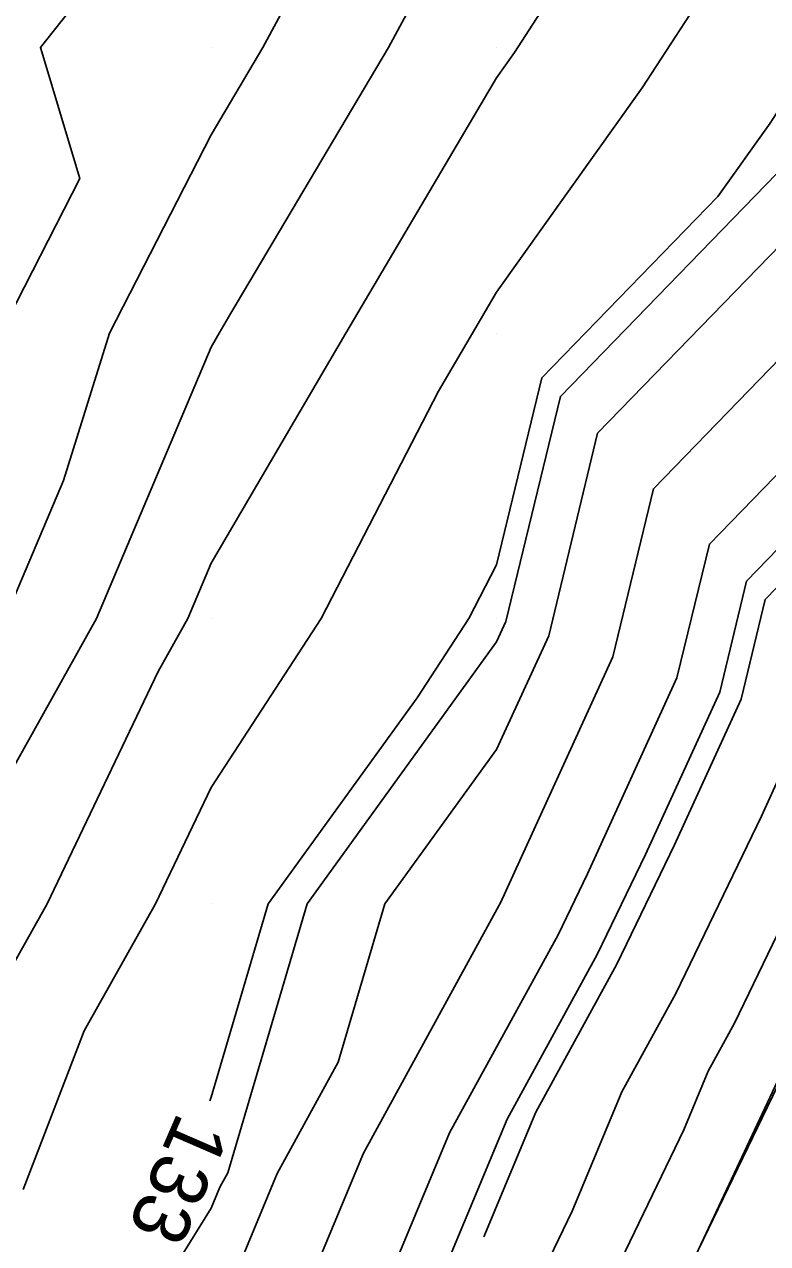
# Model space of a CAD drawing. Extents: x 2354170 to 2357230, y 866100 to 868290.
# Drawn here: x 2355193.44 to 2355219.46, y 866318.1 to 866360.82 of the extents above; entities that cross this region are included whole.
import ezdxf

# ---------------------------------------------------------------- set-up
doc = ezdxf.new("R2010")
doc.units = 0
for name, color, linetype in [('Default', 7, 'Continuous'), ('DTM Contours Major', 7, 'Continuous'), ('DTM Contours Minor', 7, 'Continuous'), ('Exist DTM QL2 LIDAR Elevation Point', 7, 'Continuous'), ('PH Exist DTM Breakline', 7, 'Continuous')]:
    doc.layers.add(name, color=color, linetype=linetype)

msp = doc.modelspace()

# ---------------------------------------------------------------- linework, layer by layer
at = {"layer": 'Default'}
for points in [[(2355191.499, 866299.8), (2355194.3, 866304.328), (2355196.889, 866310.002), (2355199.974, 866314.981), (2355202.29, 866320.553), (2355204.427, 866324.456), (2355206.063, 866330.003), (2355209.974, 866335.409), (2355211.797, 866339.401), (2355213.512, 866346.491), (2355221.537, 866354.768), (2355222.975, 866357.505), (2355230.701, 866372.146), (2355231.769, 866374.181), (2355238.322, 866388.575), (2355240.533, 866394.009), (2355250.162, 866415.374), (2355252.053, 866420.135), (2355254.413, 866426.352), (2355262.121, 866446.655), (2355264.794, 866454.48), (2355265.461, 866456.693), (2355266.805, 866460.625), (2355273.433, 866482.8)], [(2355190.844, 866286.344), (2355193.672, 866291.617), (2355196.759, 866299.104), (2355201.731, 866307.143), (2355204.812, 866313.534), (2355208.326, 866321.988), (2355212.125, 866328.925), (2355213.154, 866331.059), (2355216.287, 866337.919), (2355217.422, 866342.611), (2355222.733, 866348.088), (2355228.658, 866359.37), (2355233.375, 866368.308), (2355237.776, 866376.692), (2355241.498, 866384.869), (2355248.469, 866402.004), (2355252.795, 866411.603), (2355257.385, 866423.159), (2355258.204, 866425.317), (2355260.879, 866432.362), (2355268.147, 866453.642), (2355268.327, 866454.238), (2355272.099, 866465.271)], [(2355190.29, 866290.14), (2355194.129, 866299.452), (2355200.313, 866309.451), (2355200.907, 866310.684), (2355205.308, 866321.271), (2355210.065, 866329.957), (2355210.108, 866330.047), (2355214.042, 866338.66), (2355215.467, 866344.551), (2355222.135, 866351.428), (2355225.816, 866358.437), (2355232.038, 866370.227), (2355234.772, 866375.436), (2355239.91, 866386.722), (2355244.501, 866398.007), (2355251.479, 866413.489), (2355254.719, 866421.647), (2355256.309, 866425.835), (2355261.5, 866439.509), (2355266.47, 866454.061), (2355266.894, 866455.466), (2355269.452, 866462.948)], [(2355186.69, 866323.421), (2355189.974, 866329.157), (2355190.45, 866330.003), (2355190.883, 866330.912), (2355195.961, 866340.003), (2355199.974, 866349.514), (2355200.26, 866350.003), (2355200.672, 866350.702), (2355206.189, 866360.003), (2355209.974, 866367.025), (2355211.068, 866368.721), (2355211.919, 866370.333), (2355212.511, 866372.54), (2355215.529, 866380.003), (2355216.515, 866383.462), (2355219.974, 866388.355), (2355221.061, 866390.022), (2355221.375, 866391.404), (2355225.429, 866400.004), (2355226.321, 866403.657), (2355228.699, 866410.004), (2355229.946, 866413.048)], [(2355199.927, 866323.11), (2355199.974, 866323.23), (2355201.971, 866330.003), (2355207.193, 866337.223), (2355209.001, 866340.003), (2355209.974, 866341.886), (2355211.557, 866348.431), (2355217.719, 866354.786), (2355219.548, 866357.353), (2355220.076, 866358.171), (2355227.928, 866373.051), (2355228.294, 866374.417), (2355236.246, 866389.93), (2355236.481, 866390.29), (2355236.571, 866390.686), (2355238.576, 866394.476), (2355245.955, 866410.847)], [(2355209.531, 866318.342), (2355211.345, 866322.706), (2355214.185, 866327.893), (2355216.2, 866332.071), (2355218.532, 866337.178), (2355219.377, 866340.671), (2355223.331, 866344.748), (2355231.499, 866360.302), (2355234.712, 866366.39), (2355240.779, 866377.948), (2355243.086, 866383.016), (2355252.437, 866406.002), (2355253.237, 866407.776)], [(2355192.613, 866350.003), (2355195.385, 866355.415), (2355194.002, 866360.003), (2355199.974, 866367.561)], [(2355189.974, 866322.426), (2355194.241, 866330.003), (2355198.123, 866338.152), (2355199.157, 866340.003), (2355199.974, 866341.939), (2355204.695, 866350.003), (2355209.974, 866358.947), (2355210.602, 866359.829), (2355214.071, 866365.205)], [(2355192.766, 866340.003), (2355194.803, 866344.833), (2355196.416, 866350.003), (2355199.974, 866356.948), (2355201.785, 866360.003), (2355203.903, 866363.933)], [(2355193.232, 866276.307), (2355203.819, 866296.046), (2355204.649, 866298.059), (2355205.986, 866300.22), (2355216.526, 866322.084), (2355217.381, 866324.141), (2355218.305, 866325.829), (2355222.291, 866334.095), (2355223.022, 866335.695), (2355223.287, 866336.79), (2355224.526, 866338.068), (2355237.182, 866362.166)], [(2355193.392, 866320.003), (2355195.53, 866325.559), (2355198.033, 866330.003), (2355199.974, 866334.078), (2355203.826, 866340.003), (2355207.94, 866347.969), (2355209.131, 866350.003), (2355209.974, 866351.431), (2355215.075, 866358.591), (2355217.073, 866361.688)], [(2355192.436, 866279.652), (2355200.437, 866294.57), (2355202.019, 866298.407), (2355204.567, 866302.527), (2355212.621, 866319.234), (2355214.363, 866323.424), (2355216.245, 866326.861), (2355219.246, 866333.083), (2355220.777, 866336.436), (2355221.332, 866338.73), (2355223.928, 866341.408), (2355234.34, 866361.234)], [(2355215.75, 866315.225), (2355217.04, 866317.9), (2355220.322, 866324.685), (2355220.344, 866324.727), (2355220.368, 866324.772), (2355220.395, 866324.821), (2355225.21, 866334.753), (2355225.276, 866334.873), (2355225.345, 866335.007), (2355225.416, 866335.152), (2355225.486, 866335.304), (2355238.182, 866358.692), (2355238.772, 866359.68), (2355239.335, 866360.958)]]:
    msp.add_lwpolyline(points, dxfattribs=at)
at = {"layer": 'DTM Contours Major'}
msp.add_lwpolyline([(2355215.75, 866315.225), (2355217.04, 866317.9), (2355220.322, 866324.685), (2355220.344, 866324.727), (2355220.368, 866324.772), (2355220.395, 866324.821), (2355225.21, 866334.753), (2355225.276, 866334.873), (2355225.345, 866335.007), (2355225.416, 866335.152), (2355225.486, 866335.304), (2355238.182, 866358.692), (2355238.772, 866359.68), (2355239.335, 866360.958)], dxfattribs=at)
at = {"layer": 'DTM Contours Minor'}
for points in [[(2355190.883, 866330.912), (2355195.961, 866340.003), (2355199.974, 866349.514), (2355200.26, 866350.003), (2355200.672, 866350.702), (2355206.189, 866360.003), (2355209.974, 866367.025), (2355211.068, 866368.721), (2355211.919, 866370.333), (2355212.511, 866372.54), (2355215.529, 866380.003), (2355216.515, 866383.462), (2355219.974, 866388.355), (2355221.061, 866390.022), (2355221.375, 866391.404), (2355225.429, 866400.004), (2355226.321, 866403.657), (2355227.748, 866407.466)], [(2355189.974, 866300.771), (2355194.187, 866310.002), (2355199.974, 866319.343), (2355200.278, 866320.075), (2355200.558, 866320.587), (2355203.335, 866330.003), (2355209.974, 866339.18), (2355210.3, 866339.895), (2355212.209, 866347.785), (2355220.907, 866356.755), (2355221.038, 866356.94), (2355221.077, 866356.999), (2355229.706, 866373.352), (2355229.733, 866373.451), (2355230.474, 866374.897), (2355237.263, 866389.81), (2355237.887, 866391.344), (2355244.014, 866404.938)], [(2355191.375, 866284.113), (2355195.927, 866292.601), (2355198.513, 866298.871), (2355202.676, 866305.604), (2355207.415, 866315.434), (2355210.339, 866322.467), (2355213.498, 866328.237), (2355215.185, 866331.734), (2355217.784, 866337.425), (2355218.725, 866341.317), (2355223.131, 866345.861), (2355230.552, 866359.991), (2355234.266, 866367.029), (2355239.778, 866377.529), (2355242.557, 866383.634), (2355250.245, 866402.532)]]:
    msp.add_lwpolyline(points, dxfattribs=at)
at = {"layer": 'Exist DTM QL2 LIDAR Elevation Point'}
for p, q in [((2355199.974, 866360.003), (2355199.974, 866360.003)), ((2355209.974, 866360.003), (2355209.974, 866360.003)), ((2355199.974, 866350.003), (2355199.974, 866350.003)), ((2355209.974, 866350.003), (2355209.974, 866350.003)), ((2355199.974, 866340.003), (2355199.974, 866340.003)), ((2355209.974, 866340.003), (2355209.974, 866340.003)), ((2355199.974, 866330.003), (2355199.974, 866330.003)), ((2355209.974, 866330.003), (2355209.974, 866330.003)), ((2355199.974, 866320.003), (2355199.974, 866320.003))]:
    msp.add_line(p, q, dxfattribs=at)
at = {"layer": 'PH Exist DTM Breakline'}
msp.add_lwpolyline([(2355207.55, 866297.674), (2355225.072, 866335.019), (2355245.676, 866379.995), (2355260.219, 866424.767), (2355273.655, 866466.636), (2355281.785, 866490.339), (2355287.686, 866512.788), (2355295.16, 866540.197), (2355297.267, 866553.045), (2355302.012, 866582.828), (2355309.884, 866621.381), (2355316.964, 866662.644), (2355320.622, 866688.452), (2355323.199, 866711.282), (2355324.906, 866739.018), (2355325.362, 866751.624)], dxfattribs=at)

# ---------------------------------------------------------------- texts
at = {"layer": 'Default'}
msp.add_text('133', height=2, rotation=246.5214, dxfattribs=at).set_placement((2355198.827, 866322.767))

doc.saveas('drawing.dxf')
